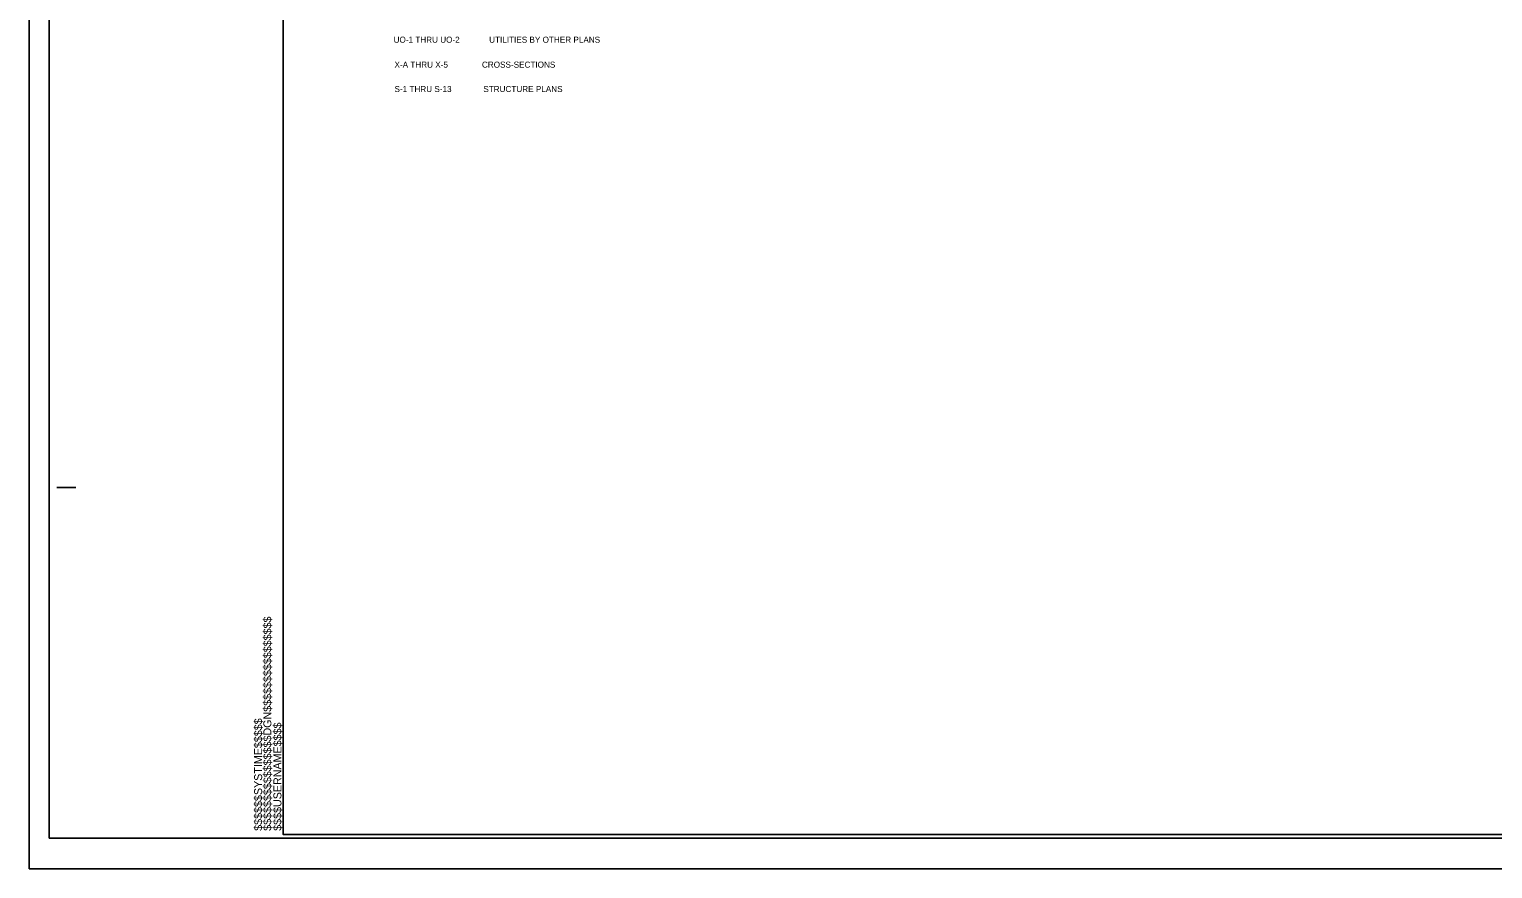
# Model space of a CAD drawing. Extents: x 573844.3 to 573878, y -53348.9 to -53327.
# Drawn here: x 573844.29 to 573863.49, y -53348.93 to -53337.92 of the extents above; entities that cross this region are included whole.
import ezdxf

# ---------------------------------------------------------------- set-up
doc = ezdxf.new("R2010")
doc.units = 0
for name, color, linetype in [('Prop Dimension Text', 7, 'Continuous'), ('Sheet Cutting Line CELL', 7, 'Continuous'), ('Sheet Plan CELL', 7, 'Continuous'), ('Sheet Plot Border Inside CELL', 7, 'Continuous'), ('Sheet Plot Border Outside CELL', 7, 'Continuous')]:
    doc.layers.add(name, color=color, linetype=linetype)

msp = doc.modelspace()

# ---------------------------------------------------------------- linework, layer by layer
at = {"layer": 'Sheet Cutting Line CELL'}
for p, q in [((573844.289, -53327.032), (573844.289, -53348.932)), ((573844.289, -53348.932), (573877.959, -53348.932))]:
    msp.add_line(p, q, dxfattribs=at)
at = {"layer": 'Sheet Plan CELL'}
for p, q in [((573844.649, -53343.932), (573844.899, -53343.932)), ((573847.619, -53348.482), (573847.619, -53348.482))]:
    msp.add_line(p, q, dxfattribs=at)
msp.add_lwpolyline([(573877.619, -53327.482), (573847.619, -53327.482), (573847.619, -53348.482), (573877.619, -53348.482)], close=True, dxfattribs=at)
at = {"layer": 'Sheet Plot Border Inside CELL'}
msp.add_lwpolyline([(573844.549, -53348.532), (573877.869, -53348.532), (573877.869, -53327.432), (573844.549, -53327.432)], close=True, dxfattribs=at)
at = {"layer": 'Sheet Plot Border Outside CELL'}
msp.add_lwpolyline([(573844.289, -53348.932), (573877.959, -53348.932), (573877.959, -53327.032), (573844.289, -53327.032)], close=True, dxfattribs=at)

# ---------------------------------------------------------------- texts
at = {"layer": 'Prop Dimension Text'}
for s, p in [('UO-1 THRU UO-2             UTILITIES BY OTHER PLANS', (573849.07, -53338.097)), ('X-A THRU X-5               CROSS-SECTIONS', (573849.082, -53338.424)), ('S-1 THRU S-13              STRUCTURE PLANS', (573849.082, -53338.744))]:
    msp.add_text(s, height=0.08, dxfattribs=at).set_placement(p)
at = {"layer": 'Sheet Plan CELL'}
for s, p in [('$$$$$$$$$$$$$$$$DGN$$$$$$$$$$$$$$$$', (573847.466, -53348.435)), ('$$$$$$SYSTIME$$$$$', (573847.345, -53348.435)), ('$$$$USERNAME$$$$', (573847.598, -53348.435))]:
    msp.add_text(s, height=0.105, rotation=90, dxfattribs=at).set_placement(p)

doc.saveas('drawing.dxf')
